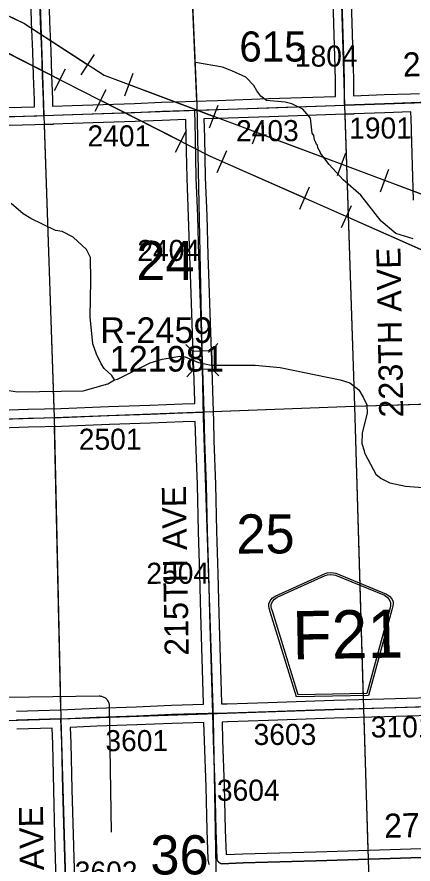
# Model space of a CAD drawing. Extents: x 128.7 to 185.5, y -21.4 to 12.6.
# Drawn here: x 145.187 to 146.502, y -12.883 to -10.071 of the extents above; entities that cross this region are included whole.
import ezdxf

# ---------------------------------------------------------------- set-up
doc = ezdxf.new("R2010")
doc.units = 0
for name, color, linetype in [('tdCoCorpBndry', 7, 'Continuous'), ('tdCoCorpPopTxt', 7, 'Continuous'), ('tdCoDirctArrow', 7, 'Continuous'), ('tdCoHydroRiver', 7, 'Continuous'), ('tdCoPipe', 7, 'Continuous'), ('tdCoSecRdNmbr', 7, 'Continuous'), ('tdCoSecRdTxt', 7, 'Continuous'), ('tdCoSecRteBand', 7, 'Continuous'), ('tdCoSecRteCL', 7, 'Continuous'), ('tdCoSectLine', 7, 'Continuous'), ('tdCoSectLinePart', 7, 'Continuous'), ('tdCoSectNmbr', 7, 'Continuous'), ('tdCoShieldCoRteHrd', 7, 'Continuous'), ('tdCoStrucSec', 7, 'Continuous'), ('tdCoStrucSecCoName', 7, 'Continuous'), ('tdCoStrucSecFHWANum', 7, 'Continuous'), ('tdCoSurfAsphalt', 7, 'Continuous'), ('tdCoSurfGravel', 7, 'Continuous'), ('tdCoTwpBndry', 7, 'Continuous'), ('tdCoTwpBndryShd', 7, 'Continuous')]:
    doc.layers.add(name, color=color, linetype=linetype)

msp = doc.modelspace()

# ---------------------------------------------------------------- linework, layer by layer
at = {"layer": 'tdCoCorpBndry'}
msp.add_lwpolyline([(147.7531, -9.6384), (147.7717, -10.312), (147.2738, -10.3304), (147.1792, -10.3333), (147.0848, -10.3364), (147.0825, -10.3365), (147.0802, -10.3366), (146.8675, -10.3436), (146.7346, -10.3483), (146.5244, -10.3548), (146.4071, -10.3587), (146.2749, -10.3634), (146.2744, -10.2811), (146.2732, -10.2373), (146.2705, -10.129), (146.2661, -9.9803)], dxfattribs=at)
at = {"layer": 'tdCoDirctArrow'}
msp.add_lwpolyline([(145.501, -12.7779), (145.4945, -12.3586), (145.4942, -12.355), (145.4939, -12.3528), (145.4932, -12.35), (145.4922, -12.3472), (145.491, -12.3445), (145.4896, -12.342), (145.488, -12.3396), (145.4861, -12.3373), (145.4841, -12.3352), (145.4819, -12.3333), (145.4795, -12.3316), (145.477, -12.3301), (145.4743, -12.3289), (145.4716, -12.3279), (145.4688, -12.3271), (145.4659, -12.3266), (145.463, -12.3263), (145.4601, -12.3263), (145.0743, -12.3317)], dxfattribs=at)
at = {"layer": 'tdCoHydroRiver'}
for points in [[(146.5027, -10.807), (146.4453, -10.7899), (146.3966, -10.7489), (146.3291, -10.6628), (146.2706, -10.611), (146.2232, -10.5605), (146.1951, -10.5235), (146.195, -10.5204), (146.1866, -10.5049), (146.1848, -10.497), (146.1815, -10.494), (146.1797, -10.4877), (146.1747, -10.4784), (146.1727, -10.4643), (146.1677, -10.4566), (146.1613, -10.4063), (146.1367, -10.3771), (146.0998, -10.3593), (146.0775, -10.3538), (146.0158, -10.3479), (145.9964, -10.3343), (145.9832, -10.3158), (145.9731, -10.2988), (145.947, -10.2712), (145.9005, -10.2491), (145.8701, -10.2375), (145.7796, -10.2215)], [(145.5111, -11.2751), (145.5027, -11.2612), (145.4767, -11.2383), (145.4668, -11.2229), (145.4515, -11.1902), (145.4393, -11.1559), (145.4301, -11.0663), (145.4325, -10.9462), (145.4315, -10.8689), (145.418, -10.8425), (145.3741, -10.8014), (145.3372, -10.7836), (145.3149, -10.7796), (145.2331, -10.7397), (145.2074, -10.7248), (145.1684, -10.6897)], [(145.146, -11.3091), (145.1889, -11.3156), (145.4065, -11.3117), (145.4894, -11.2884), (145.5111, -11.2751), (145.5205, -11.2732), (145.6292, -11.2191), (145.6698, -11.2068), (145.7279, -11.197), (145.7454, -11.1996), (145.7902, -11.2186), (145.8315, -11.2267), (145.9783, -11.2266), (146.0606, -11.235), (146.2608, -11.2758), (146.2927, -11.2858), (146.3218, -11.3085), (146.3369, -11.3333), (146.3487, -11.3581), (146.3497, -11.3865), (146.3329, -11.4518), (146.3324, -11.4865), (146.3395, -11.5115), (146.3413, -11.5178), (146.3431, -11.5225), (146.3784, -11.5892), (146.3962, -11.6028), (146.4251, -11.6176), (146.4775, -11.6285), (146.563, -11.6352)]]:
    msp.add_lwpolyline(points, dxfattribs=at)
at = {"layer": 'tdCoPipe'}
for p, q in [((145.4008, -10.2634), (145.4445, -10.1957)), ((145.3118, -10.3145), (145.3482, -10.243)), ((145.5448, -10.3329), (145.573, -10.2576)), ((145.4468, -10.3833), (145.4832, -10.3119)), ((145.8268, -10.4386), (145.8551, -10.3631)), ((145.9693, -10.492), (145.9975, -10.4166)), ((145.7141, -10.5195), (145.7506, -10.4479)), ((145.8521, -10.5871), (145.8845, -10.5138)), ((146.2513, -10.5976), (146.2796, -10.5221)), ((146.3938, -10.651), (146.422, -10.5756)), ((146.1264, -10.7085), (146.1589, -10.635)), ((146.265, -10.7698), (146.2974, -10.6965))]:
    msp.add_line(p, q, dxfattribs=at)
for points in [[(133.6945, 0.4089), (135.1153, -0.6342), (137.1324, -2.3792), (137.5288, -2.9528), (138.161, -3.328), (139.2218, -4.4833), (139.3397, -4.805), (140.8827, -6.1264), (141.2631, -6.6089), (142.2971, -8.0348), (142.3319, -8.2734), (143.9392, -9.367), (143.9927, -9.5975), (145.829, -10.533), (147.4283, -11.2406), (148.0149, -11.3532), (148.9915, -11.5772), (150.6773, -11.7094), (151.6631, -11.8649), (152.1578, -12.9549), (152.0489, -14.0003)], [(141.7836, -7.0033), (142.3273, -7.8596), (142.3925, -8.1335), (142.8785, -8.3933), (143.1849, -8.6984), (143.96, -9.2344), (144.0145, -9.2874), (144.0511, -9.4993), (144.1965, -9.5563), (144.4517, -9.5354), (144.51, -9.7346), (144.8087, -9.8976), (145.2095, -10.0919), (145.4764, -10.2643), (147.4123, -10.9894), (147.8261, -11.2583), (148.2617, -11.2593), (148.6573, -11.4241), (149.6319, -11.4948), (151.5237, -11.7631), (152.8427, -11.7734), (156.2861, -11.7117)], [(145.1668, -10.0712), (145.2095, -10.0919), (145.4227, -10.2296)], [(145.0627, -10.1426), (145.33, -10.2788)], [(145.5589, -10.2952), (145.841, -10.4008)], [(145.465, -10.3475), (145.7323, -10.4837)], [(145.9834, -10.4542), (146.2655, -10.5599)], [(145.8683, -10.5504), (146.1427, -10.6718)], [(146.4079, -10.6132), (146.69, -10.7189)], [(146.2812, -10.7331), (146.5556, -10.8545)]]:
    msp.add_lwpolyline(points, dxfattribs=at)
at = {"layer": 'tdCoSecRteBand'}
for points in [[(145.1154, -10.3726), (145.2457, -10.3693), (145.2449, -10.3464), (145.2422, -10.266), (145.2422, -10.266), (145.2422, -10.266), (145.2395, -10.1852), (145.2358, -10.0876), (145.2358, -10.0875), (145.2358, -10.0874), (145.2318, -9.9619)], [(145.2918, -9.96), (145.2957, -10.0854), (145.2994, -10.183), (145.2994, -10.1831), (145.2994, -10.1831), (145.3022, -10.264), (145.3049, -10.3444), (145.3049, -10.3444), (145.3049, -10.3444), (145.3056, -10.3673), (145.3705, -10.365), (145.4729, -10.3613), (145.4729, -10.3613), (145.473, -10.3613), (145.5772, -10.3578), (145.6671, -10.3541), (145.6672, -10.3541), (145.6673, -10.3541), (145.7467, -10.3515), (145.7467, -10.3512), (145.7766, -10.3505), (145.8525, -10.3479), (146.0226, -10.342), (146.0226, -10.342), (146.0226, -10.342), (146.2439, -10.3345), (146.2447, -10.3345), (146.2444, -10.2817), (146.2432, -10.2381), (146.2432, -10.238), (146.2432, -10.238), (146.2405, -10.1298), (146.2361, -9.9812)], [(146.2961, -9.9795), (146.3005, -10.1281), (146.3005, -10.1282), (146.3005, -10.1282), (146.3032, -10.2365), (146.3044, -10.2803), (146.3044, -10.2806), (146.3044, -10.281), (146.3047, -10.3324), (146.406, -10.3287), (146.4061, -10.3287), (146.4061, -10.3287), (146.4936, -10.3258), (146.4936, -10.3257), (146.5235, -10.3248)], [(146.5041, -10.6787), (146.4992, -10.5256), (146.4992, -10.5255), (146.4992, -10.5254), (146.496, -10.4076), (146.4953, -10.3858), (146.4082, -10.3887), (146.3059, -10.3924), (146.3059, -10.3924), (146.3051, -10.3924), (146.3051, -10.3933), (146.2755, -10.3934), (146.0247, -10.402), (145.8545, -10.4079), (145.8545, -10.4079), (145.8545, -10.4079), (145.8084, -10.4094), (145.8081, -10.4095), (145.8095, -10.4704), (145.8095, -10.4704), (145.8095, -10.4704), (145.8125, -10.6038), (145.8171, -10.7309), (145.8171, -10.731), (145.8171, -10.7312), (145.8206, -10.8619), (145.8255, -10.9873), (145.8255, -10.9873), (145.8255, -10.9874), (145.83, -11.1184), (145.83, -11.1184), (145.83, -11.1184), (145.8339, -11.241), (145.8374, -11.3448), (145.8374, -11.3449), (145.8374, -11.3449), (145.8384, -11.3816), (145.8396, -11.4114), (145.8392, -11.4115), (145.8411, -11.477), (145.8465, -11.6226), (145.8465, -11.6228), (145.8465, -11.623), (145.8499, -11.7783), (145.8541, -11.9192), (145.8541, -11.9193), (145.8541, -11.9193), (145.8578, -12.0512), (145.862, -12.2001), (145.8667, -12.3478), (145.8667, -12.3479), (145.8667, -12.3481), (145.8668, -12.3516), (145.8668, -12.3517)], [(145.0698, -11.3784), (145.2238, -11.373), (145.2241, -11.373), (145.2243, -11.373), (145.3332, -11.3708), (145.4914, -11.3641), (145.4915, -11.3641), (145.4916, -11.3641), (145.6285, -11.3592), (145.6285, -11.3592), (145.6285, -11.3592), (145.7365, -11.3555), (145.7776, -11.3539), (145.7776, -11.3535), (145.7774, -11.3467), (145.7739, -11.243), (145.7739, -11.2429), (145.7739, -11.2429), (145.77, -11.1204), (145.7656, -10.9895), (145.7606, -10.8641), (145.7606, -10.8639), (145.7606, -10.8637), (145.7572, -10.7329), (145.7525, -10.6058), (145.7525, -10.6056), (145.7525, -10.6054), (145.7495, -10.4717), (145.7481, -10.4114), (145.6694, -10.4141), (145.5795, -10.4178), (145.5794, -10.4178), (145.5793, -10.4178), (145.475, -10.4212), (145.3727, -10.4249), (145.3727, -10.4249), (145.3727, -10.4249), (145.3077, -10.4272), (145.3076, -10.4272), (145.3076, -10.4273), (145.2777, -10.4283), (145.2477, -10.4293), (145.2477, -10.4293), (145.2477, -10.4293), (145.2477, -10.4293), (145.117, -10.4326)], [(145.1854, -12.3758), (145.332, -12.3713), (145.4502, -12.3654), (145.4505, -12.3654), (145.4508, -12.3654), (145.5833, -12.3614), (145.7004, -12.3563), (145.7006, -12.3563), (145.7008, -12.3563), (145.8068, -12.353), (145.8067, -12.3495), (145.802, -12.202), (145.802, -12.2019), (145.802, -12.2019), (145.7979, -12.0529), (145.7979, -12.0529), (145.7942, -11.921), (145.79, -11.78), (145.79, -11.7798), (145.79, -11.7797), (145.7865, -11.6246), (145.7811, -11.4791), (145.7811, -11.4789), (145.7811, -11.4788), (145.7793, -11.4138), (145.7388, -11.4155), (145.7387, -11.4155), (145.7386, -11.4155), (145.6306, -11.4192), (145.4939, -11.4241), (145.3354, -11.4307), (145.3351, -11.4308), (145.3347, -11.4308), (145.2257, -11.433), (145.0706, -11.4384)], [(145.8668, -12.3517), (145.8669, -12.3517), (145.8852, -12.3513), (146.0201, -12.3469), (146.2388, -12.3395), (146.2389, -12.3395), (146.2389, -12.3395), (146.4051, -12.3343), (146.4052, -12.3343), (146.4052, -12.3343), (146.5576, -12.3301)], [(146.5597, -12.3901), (146.4069, -12.3943), (146.2408, -12.3995), (146.0221, -12.4068), (146.0221, -12.4068), (146.0221, -12.4068), (145.8869, -12.4113), (145.8867, -12.4113), (145.8865, -12.4113), (145.8681, -12.4117), (145.8694, -12.4719), (145.8748, -12.6246), (145.8748, -12.6247), (145.8748, -12.6248), (145.879, -12.7693), (145.8816, -12.8514)], [(145.8265, -12.8857), (145.8254, -12.8833), (145.8244, -12.8811), (145.8238, -12.8787), (145.8232, -12.8762), (145.8226, -12.8738), (145.8224, -12.8714), (145.8221, -12.8688), (145.8221, -12.8679), (145.822, -12.867), (145.8191, -12.7711), (145.8191, -12.7711), (145.8191, -12.771), (145.8149, -12.6266), (145.8095, -12.4738), (145.8094, -12.4736), (145.8094, -12.4734), (145.8081, -12.413), (145.7029, -12.4162), (145.5857, -12.4214), (145.5855, -12.4214), (145.5853, -12.4214), (145.4529, -12.4253), (145.3642, -12.4298), (145.366, -12.4818), (145.366, -12.4819), (145.366, -12.4821), (145.3695, -12.6362), (145.3734, -12.7851), (145.3778, -12.9386)], [(145.3179, -12.9404), (145.3134, -12.7868), (145.3134, -12.7867), (145.3134, -12.7867), (145.3095, -12.6377), (145.3095, -12.6377), (145.3095, -12.6376), (145.306, -12.4837), (145.3042, -12.4322), (145.1872, -12.4358), (145.1871, -12.4358)], [(145.8816, -12.8514), (145.9367, -12.849), (145.937, -12.849), (145.9373, -12.8489), (146.1801, -12.8428), (146.4259, -12.8349), (146.4259, -12.8349), (146.4259, -12.8349), (146.6306, -12.8287)]]:
    msp.add_lwpolyline(points, dxfattribs=at)
at = {"layer": 'tdCoSecRteCL'}
for points in [[(145.2767, -10.3983), (145.2749, -10.3454), (145.2722, -10.265), (145.2695, -10.1841), (145.2658, -10.0865), (145.2618, -9.961), (145.2586, -9.8562), (145.2549, -9.7405), (145.2512, -9.6372), (145.2473, -9.5052), (145.245, -9.4569), (145.2433, -9.4066), (145.2436, -9.3971), (145.2438, -9.3903), (145.2413, -9.3371), (145.2389, -9.2576), (145.2352, -9.1494), (145.2305, -9.0236), (145.227, -8.9025), (145.2238, -8.7883), (145.2184, -8.6631), (145.2145, -8.5232), (145.211, -8.3948)], [(146.2749, -10.3634), (146.2744, -10.2811), (146.2732, -10.2373), (146.2705, -10.129), (146.2661, -9.9803), (146.2641, -9.8974), (146.2641, -9.8973)], [(145.7774, -10.3805), (145.8535, -10.3779), (146.0236, -10.372), (146.2749, -10.3634)], [(146.2749, -10.3634), (146.2986, -10.3626), (146.4071, -10.3587), (146.5244, -10.3548)], [(143.2711, -10.4636), (143.4935, -10.4566), (143.764, -10.4475), (143.908, -10.4433), (144.0745, -10.4376), (144.3822, -10.4287), (144.5632, -10.4216), (144.8648, -10.4117), (145.0096, -10.4063), (145.1161, -10.4026), (145.2532, -10.3991), (145.2767, -10.3983)], [(145.2767, -10.3983), (145.3716, -10.3949), (145.474, -10.3912), (145.5783, -10.3878), (145.6683, -10.3841), (145.7774, -10.3805)], [(145.8084, -11.3827), (145.8074, -11.3458), (145.8039, -11.242), (145.8, -11.1194), (145.7955, -10.9884), (145.7906, -10.8629), (145.7872, -10.732), (145.7825, -10.6047), (145.7795, -10.4711), (145.7774, -10.3805)], [(144.3058, -11.4329), (144.3433, -11.4309), (144.3926, -11.4309), (144.6074, -11.4232), (144.7452, -11.4193), (144.8076, -11.4161), (144.8436, -11.4104), (144.981, -11.4074), (145.038, -11.4067), (145.0695, -11.4084), (145.2249, -11.403), (145.3341, -11.4008), (145.4927, -11.3941), (145.6296, -11.3892), (145.7376, -11.3855), (145.8084, -11.3827)], [(145.8375, -12.3822), (145.8367, -12.3487), (145.832, -12.201), (145.8278, -12.0521), (145.8241, -11.9201), (145.82, -11.7791), (145.8165, -11.6237), (145.8111, -11.478), (145.8084, -11.3827)], [(145.8375, -12.3822), (145.886, -12.3813), (146.0211, -12.3769), (146.2398, -12.3695), (146.4061, -12.3643), (146.5597, -12.3601), (146.5887, -12.3591)], [(144.3336, -12.4318), (144.3504, -12.4313), (144.4737, -12.4272), (144.5586, -12.4249), (144.6706, -12.4214), (144.7489, -12.4188), (144.8502, -12.4159), (144.9367, -12.4126), (145.0506, -12.4093), (145.1862, -12.4058), (145.3332, -12.4013)], [(145.3332, -12.4013), (145.4517, -12.3954), (145.5844, -12.3914), (145.7017, -12.3862), (145.8223, -12.3825), (145.8375, -12.3822)], [(145.3698, -13.7221), (145.3696, -13.705), (145.3654, -13.5605), (145.3614, -13.3987), (145.3572, -13.2458), (145.353, -13.0951), (145.3479, -12.9395), (145.3434, -12.7859), (145.3395, -12.6369), (145.336, -12.4828), (145.3332, -12.4013)], [(146.8528, -12.8515), (146.6315, -12.8587), (146.4268, -12.8649), (146.181, -12.8728), (145.9381, -12.8789), (145.8666, -12.8821), (145.864, -12.8817), (145.8615, -12.8808), (145.8592, -12.8795), (145.8572, -12.8778), (145.856, -12.8765), (145.8554, -12.8759), (145.854, -12.8737), (145.8529, -12.8713), (145.8522, -12.8687), (145.852, -12.8661), (145.849, -12.7702), (145.8449, -12.6257), (145.8394, -12.4728), (145.8375, -12.3822)]]:
    msp.add_lwpolyline(points, dxfattribs=at)
at = {"layer": 'tdCoSectLine'}
for points in [[(146.2452, -9.3614), (146.2741, -10.3635)], [(145.2432, -9.3971), (145.2763, -10.3983)], [(146.2741, -10.3635), (147.2734, -10.3304)], [(145.2763, -10.3983), (146.2741, -10.3635)], [(146.2741, -10.3635), (146.3081, -11.3633)], [(144.2751, -10.4318), (145.2763, -10.3983)], [(145.2763, -10.3983), (145.3104, -11.4012)], [(146.3081, -11.3633), (147.304, -11.3321)], [(145.3104, -11.4012), (146.3081, -11.3633)], [(146.3081, -11.3633), (146.3377, -12.3666)], [(144.3055, -11.4329), (145.3104, -11.4012)], [(145.3104, -11.4012), (145.3328, -12.4013)], [(146.3377, -12.3666), (147.3379, -12.335)], [(145.3328, -12.4013), (146.3377, -12.3666)], [(146.3377, -12.3666), (146.369, -13.3685)], [(144.3332, -12.4318), (145.3328, -12.4013)], [(145.3328, -12.4013), (145.3611, -13.3996)]]:
    msp.add_lwpolyline(points, dxfattribs=at)
at = {"layer": 'tdCoSectLinePart'}
for points in [[(146.2752, -10.3933), (146.3081, -11.3633)], [(145.2773, -10.4283), (145.3093, -11.3713)], [(146.3081, -11.3633), (146.527, -11.3565)], [(145.838, -11.3812), (146.3081, -11.3633)], [(146.3081, -11.3633), (146.3368, -12.3371)], [(145.311, -11.4312), (145.3321, -12.3713)], [(146.3386, -12.397), (146.3524, -12.8374)]]:
    msp.add_lwpolyline(points, dxfattribs=at)
at = {"layer": 'tdCoShieldCoRteHrd'}
for points in [[(146.1152, -12.3278), (146.0283, -12.0464), (146.0242, -12.0333), (146.0234, -12.0274), (146.0233, -12.0196), (146.0273, -12.0092), (146.0344, -12.0006), (146.0439, -11.9938), (146.2099, -11.9185), (146.2174, -11.9168), (146.2278, -11.9157), (146.2382, -11.9164), (146.2458, -11.9179), (146.4143, -11.9873), (146.424, -11.9938), (146.4314, -12.0022), (146.4358, -12.0124), (146.4359, -12.0202), (146.4353, -12.0261), (146.4317, -12.0394), (146.3547, -12.3236)], [(146.1209, -12.3214), (146.0364, -12.0475), (146.0325, -12.035), (146.0317, -12.0293), (146.0315, -12.0218), (146.0354, -12.0119), (146.0423, -12.0036), (146.0514, -11.997), (146.2107, -11.9248), (146.2179, -11.9231), (146.2279, -11.922), (146.2379, -11.9227), (146.2452, -11.9242), (146.4069, -11.9908), (146.4162, -11.9971), (146.4234, -12.0051), (146.4276, -12.0149), (146.4277, -12.0224), (146.4271, -12.0281), (146.4236, -12.0408), (146.3487, -12.3174)]]:
    msp.add_lwpolyline(points, close=True, dxfattribs=at)
at = {"layer": 'tdCoStrucSec'}
for p, q in [((145.7702, -11.1801), (145.7474, -11.1587)), ((145.8328, -11.1781), (145.8542, -11.1552)), ((145.7722, -11.2426), (145.7508, -11.2655)), ((145.8348, -11.2406), (145.8576, -11.262))]:
    msp.add_line(p, q, dxfattribs=at)
msp.add_lwpolyline([(145.7722, -11.2426), (145.7702, -11.1801), (145.8328, -11.1781), (145.8348, -11.2406)], close=True, dxfattribs=at)
at = {"layer": 'tdCoSurfAsphalt'}
for points in [[(145.3332, -12.4013), (145.4517, -12.3954), (145.5844, -12.3914), (145.7017, -12.3862), (145.8223, -12.3825), (145.8375, -12.3822), (145.886, -12.3813), (146.0211, -12.3769), (146.2398, -12.3695), (146.4061, -12.3643), (146.5597, -12.3601)], [(145.3332, -12.4013), (145.1862, -12.4058)], [(145.3698, -13.7221), (145.3696, -13.705), (145.3654, -13.5605), (145.3614, -13.3987), (145.3572, -13.2458), (145.353, -13.0951), (145.3479, -12.9395), (145.3434, -12.7859), (145.3395, -12.6369), (145.336, -12.4828), (145.3332, -12.4013)]]:
    msp.add_lwpolyline(points, dxfattribs=at)
at = {"layer": 'tdCoSurfGravel'}
for points in [[(146.2749, -10.3634), (146.2744, -10.2811), (146.2732, -10.2373), (146.2705, -10.129), (146.2661, -9.9803), (146.2641, -9.8974)], [(145.2767, -10.3983), (145.2749, -10.3454), (145.2722, -10.265), (145.2695, -10.1841), (145.2658, -10.0865), (145.2618, -9.961)], [(146.2749, -10.3634), (146.2986, -10.3626), (146.4071, -10.3587), (146.5244, -10.3548), (146.54, -10.3543), (146.7346, -10.3483), (146.8675, -10.3436), (147.1792, -10.3333), (147.2738, -10.3304)], [(143.2711, -10.4636), (143.4935, -10.4566), (143.764, -10.4475), (143.908, -10.4433), (144.0745, -10.4376), (144.3822, -10.4287), (144.5632, -10.4216), (144.8648, -10.4117), (145.0096, -10.4063), (145.1161, -10.4026), (145.2532, -10.3991), (145.2767, -10.3983), (145.3716, -10.3949), (145.474, -10.3912), (145.5783, -10.3878), (145.6683, -10.3841), (145.7774, -10.3805), (145.8535, -10.3779), (146.0236, -10.372), (146.2749, -10.3634)], [(145.856, -12.8765), (145.8554, -12.8759), (145.854, -12.8737), (145.8529, -12.8713), (145.8522, -12.8687), (145.852, -12.8661), (145.849, -12.7702), (145.8449, -12.6257), (145.8394, -12.4728), (145.8375, -12.3822), (145.8367, -12.3487), (145.832, -12.201), (145.8278, -12.0521), (145.8241, -11.9201), (145.82, -11.7791), (145.8165, -11.6237), (145.8111, -11.478), (145.8084, -11.3827), (145.8074, -11.3458), (145.8039, -11.242), (145.8, -11.1194), (145.7955, -10.9884), (145.7906, -10.8629), (145.7872, -10.732), (145.7825, -10.6047), (145.7795, -10.4711), (145.7774, -10.3805)], [(143.3023, -11.4632), (143.4256, -11.458), (143.5864, -11.4545), (143.7714, -11.4484), (143.9068, -11.4444), (144.0861, -11.4397), (144.2838, -11.4341), (144.3058, -11.4329), (144.3433, -11.4309), (144.3926, -11.4309), (144.6074, -11.4232), (144.7452, -11.4193), (144.8076, -11.4161), (144.8436, -11.4104), (144.981, -11.4074), (145.038, -11.4067), (145.0695, -11.4084), (145.2249, -11.403), (145.3341, -11.4008), (145.4927, -11.3941), (145.6296, -11.3892), (145.7376, -11.3855), (145.8084, -11.3827)], [(145.856, -12.8765), (145.8572, -12.8778), (145.8592, -12.8795), (145.8615, -12.8808), (145.864, -12.8817), (145.8666, -12.8821), (145.9381, -12.8789), (146.181, -12.8728), (146.4268, -12.8649), (146.6315, -12.8587), (146.8528, -12.8515), (146.9033, -12.8498), (147.0942, -12.8434), (147.0966, -12.8423), (147.0989, -12.8408), (147.1008, -12.8389), (147.1024, -12.8366), (147.1035, -12.8342), (147.1041, -12.8323)]]:
    msp.add_lwpolyline(points, dxfattribs=at)
at = {"layer": 'tdCoTwpBndry'}
msp.add_lwpolyline([(145.7843, -10.3501), (145.7006, -8.4088)], dxfattribs=at)
at = {"layer": 'tdCoTwpBndryShd'}
msp.add_lwpolyline([(145.6562, -7.3766), (145.6798, -7.9257), (145.6983, -8.3554), (145.7848, -10.3621), (145.8056, -11.4012), (145.8383, -12.3992), (145.8518, -13.146), (146.153, -13.1454), (146.1544, -13.861)], dxfattribs=at)

# ---------------------------------------------------------------- texts
at = {"layer": 'tdCoCorpPopTxt'}
msp.add_text('615', height=0.1, dxfattribs=at).set_placement((145.9255, -10.2188))
at = {"layer": 'tdCoSecRdNmbr'}
for s, rotation, p in [('1804', 0.1109, (146.1101, -10.2358)), ('1901', 0.1109, (146.2902, -10.4747)), ('2401', 0.1102, (145.4214, -10.5008)), ('2403', 0.1106, (145.9146, -10.4835)), ('2404', 0.1103, (145.5868, -10.8811)), ('2501', 0.1102, (145.3926, -11.508)), ('2504', 0.1103, (145.6169, -11.953)), ('3101', 0.1109, (146.3619, -12.4631)), ('3603', 0.1106, (145.9729, -12.4881)), ('3601', 0.1102, (145.4808, -12.5087)), ('3604', 0.1106, (145.8511, -12.6733)), ('3602', 0.1101, (145.3792, -12.9449))]:
    msp.add_text(s, height=0.07, rotation=rotation, dxfattribs=at).set_placement(p)
at = {"layer": 'tdCoSecRdTxt'}
for s, rotation, p in [('250TH ST', 1.9993, (146.4696, -10.2692)), ('223TH AVE', 91, (146.4701, -11.3999)), ('215TH AVE', 91, (145.7578, -12.1912)), ('210TH AVE', 91, (145.2832, -13.2543)), ('275 ST', 1.5803, (146.4072, -12.7966))]:
    msp.add_text(s, height=0.08, rotation=rotation, dxfattribs=at).set_placement(p)
at = {"layer": 'tdCoSectNmbr'}
for s, p in [('24', (145.5835, -10.9447)), ('25', (145.9156, -11.8523)), ('36', (145.6303, -12.918))]:
    msp.add_text(s, height=0.13, rotation=0.1105, dxfattribs=at).set_placement(p)
at = {"layer": 'tdCoShieldCoRteHrd'}
msp.add_text('F21', height=0.16, rotation=1, dxfattribs=at).set_placement((146.1024, -12.2038))
at = {"layer": 'tdCoStrucSecCoName'}
msp.add_text('R-2459', height=0.085, dxfattribs=at).set_placement((145.4638, -11.1532))
at = {"layer": 'tdCoStrucSecFHWANum'}
msp.add_text('121981', height=0.085, dxfattribs=at).set_placement((145.4951, -11.2481))

doc.saveas('drawing.dxf')
